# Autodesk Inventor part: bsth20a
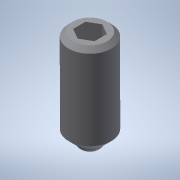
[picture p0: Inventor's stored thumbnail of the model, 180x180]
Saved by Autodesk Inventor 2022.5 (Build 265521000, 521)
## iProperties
Created: 2016-12
Part Number: bsth20a
Material: 一般
Document SubType Name: Modeling
Designer: imaocorp
Density: 1 g/cm^3
Appearance: 既定
Author: imaocorp
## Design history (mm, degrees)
node "bsth20a.x_t1"
node "bsth20a"
node "Base1"
